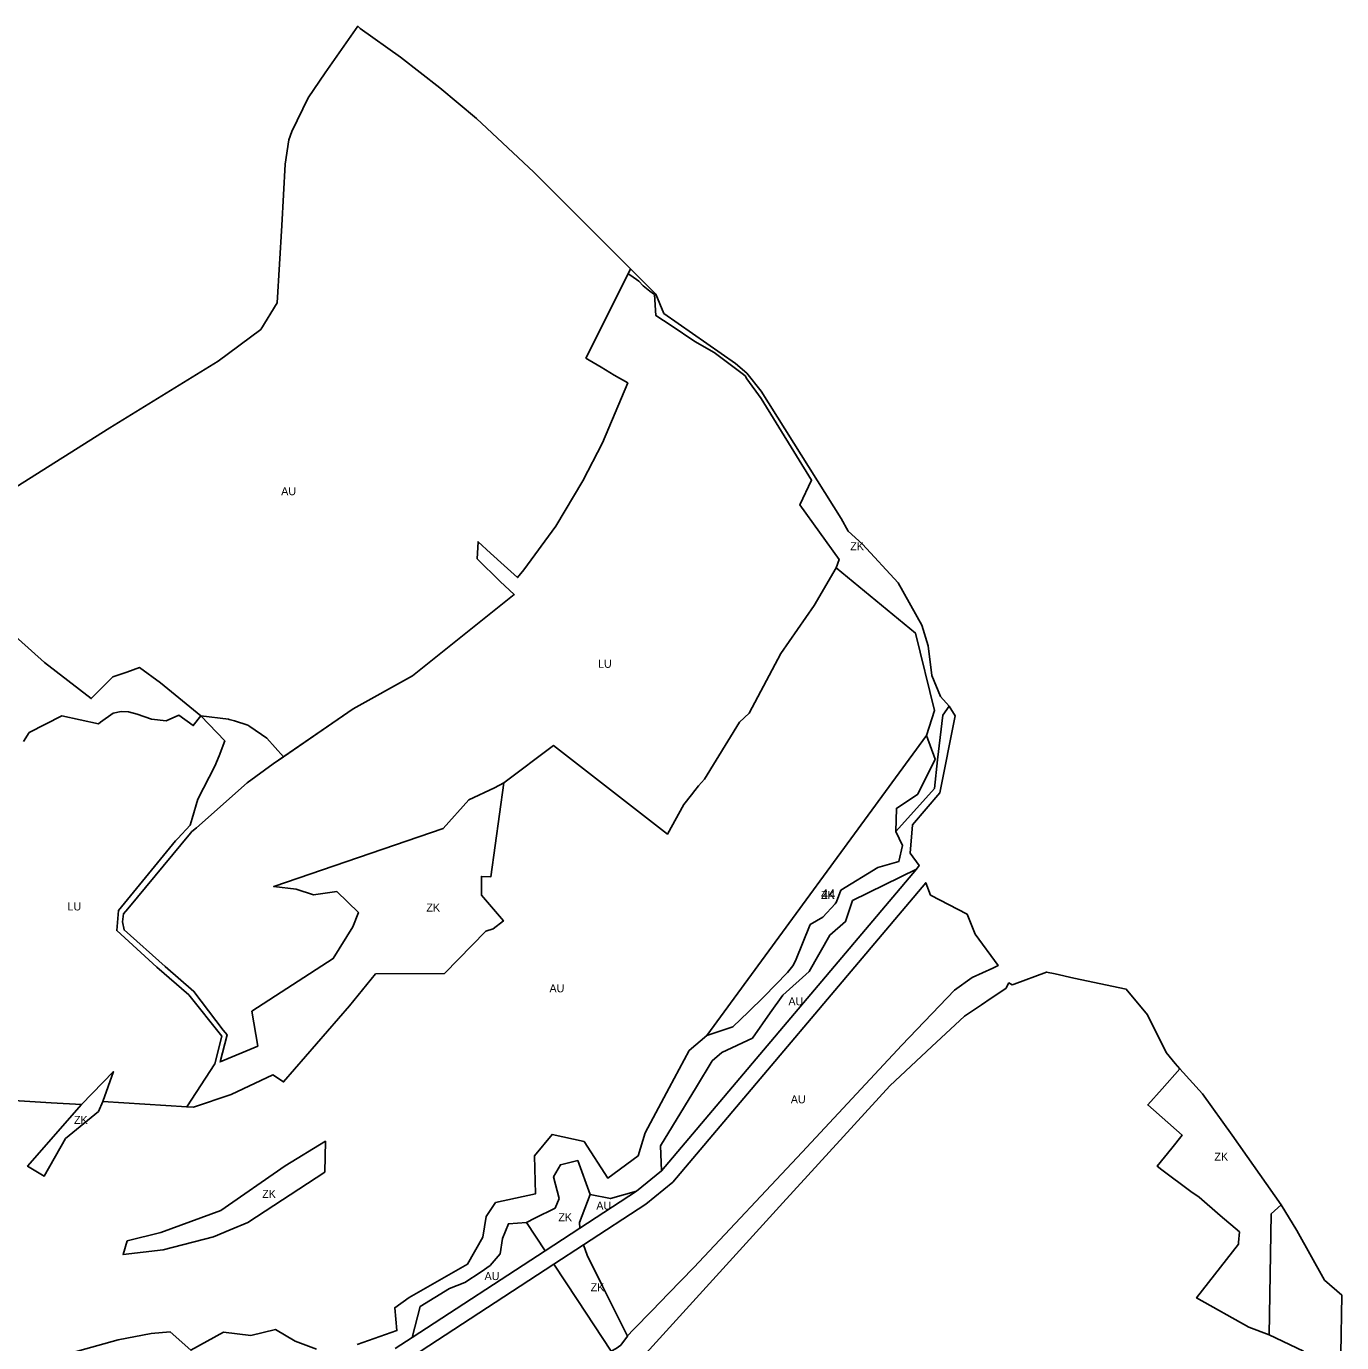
# Model space of a CAD drawing. Extents: x -521261 to -517465, y -1182764 to -1179456.
# Drawn here: x -519568 to -518746, y -1180279 to -1179456 of the extents above; entities that cross this region are included whole.
import ezdxf

# ---------------------------------------------------------------- set-up
doc = ezdxf.new("R2010")
doc.units = 0
for name, color, linetype in [('90640013', 7, 'Continuous'), ('90710013', 7, 'Continuous'), ('90710023', 7, 'Continuous'), ('90750013', 7, 'Continuous'), ('90770013', 7, 'Continuous'), ('ID_navrh', 7, 'Continuous')]:
    doc.layers.add(name, color=color, linetype=linetype)

msp = doc.modelspace()

# ---------------------------------------------------------------- linework, layer by layer
at = {"layer": '90640013'}
for points in [[(-519361.62, -1180279.74), (-519336.67, -1180271.06), (-519338.06, -1180256.8), (-519329.08, -1180250.31), (-519292.48, -1180229.49), (-519282.89, -1180212.77), (-519280.86, -1180199.88), (-519274.99, -1180191.09), (-519249.97, -1180185.55), (-519250.61, -1180161.86), (-519239.69, -1180148.52), (-519219.72, -1180152.85), (-519204.93, -1180175.78), (-519185.89, -1180161.84), (-519181.51, -1180147.48), (-519166.43, -1180119.32), (-519153.96, -1180096.09), (-519142.9, -1180086.6), (-519126.81, -1180081.34), (-519116.98, -1180071.93), (-519107.29, -1180062.58), (-519092.52, -1180047.19), (-519089.17, -1180043.17), (-519087.64, -1180039.96), (-519078.39, -1180017.36), (-519070.55, -1180012.74), (-519062.74, -1180004.36), (-519061.82, -1180003.21), (-519059.13, -1179995.85), (-519035.98, -1179981.57), (-519022.98, -1179978.01), (-519020.57, -1179968.01), (-519024.91, -1179959.15), (-519000.72, -1179932.26), (-518998.7, -1179914.28), (-518995.5, -1179886.53), (-518991.43, -1179880.86), (-518987.68, -1179886.81), (-518997.22, -1179934.93), (-519014.39, -1179955.1), (-519015.83, -1179972.69), (-519010.33, -1179980.49), (-519011.96, -1179982.64), (-519051.9, -1180002.3), (-519056.3, -1180015.44), (-519066.13, -1180023.9), (-519078.94, -1180046.61), (-519095.37, -1180061.41), (-519103.39, -1180072.53), (-519114.42, -1180088.31), (-519133.53, -1180097.26), (-519139.57, -1180102.58), (-519149.41, -1180118.82), (-519171.97, -1180155.54), (-519171.27, -1180171.17), (-519186.97, -1180183.94), (-519203.21, -1180188.59), (-519215.87, -1180186.06), (-519223.62, -1180164.85), (-519234.47, -1180167.48), (-519238.76, -1180175.07), (-519235.32, -1180188.57), (-519237.84, -1180194.65), (-519250.47, -1180200.79), (-519255.66, -1180203.54), (-519267, -1180204.34), (-519270.72, -1180213.62), (-519272.1, -1180223.08), (-519278.49, -1180230.4), (-519284, -1180234.4), (-519294.17, -1180241.09), (-519303.81, -1180244.74), (-519322.14, -1180255.98), (-519327.14, -1180275.48), (-519337.72, -1180282.23)], [(-519540.12, -1180284.95), (-519510.88, -1180276.77), (-519490.4, -1180273), (-519478.49, -1180271.77), (-519465.42, -1180283.42), (-519445.16, -1180272.07), (-519428.03, -1180274.15), (-519412.68, -1180270.41), (-519400.33, -1180277.79), (-519386.97, -1180282.76)]]:
    msp.add_lwpolyline(points, dxfattribs=at)
at = {"layer": '90710013'}
for points in [[(-519077.44, -1179739.61), (-519109.05, -1179688.57), (-519117.88, -1179676.19), (-519119.05, -1179674.41), (-519120.9, -1179672.9), (-519138.3, -1179659.87), (-519150.46, -1179652.92), (-519165.33, -1179642.89), (-519174.76, -1179636.77), (-519175.76, -1179623.57), (-519178.68, -1179621.38), (-519182.72, -1179618.14), (-519185.56, -1179615.32), (-519190.55, -1179611.67), (-519192.16, -1179610.6), (-519190.638, -1179607.556), (-519174.91, -1179623.36), (-519169.82, -1179635.35), (-519124.96, -1179666.62), (-519118.02, -1179672.77), (-519109.01, -1179683.98), (-519058.98, -1179763.47), (-519054.55, -1179771.52), (-519045.59, -1179779.49), (-519023.39, -1179803.85), (-519008.51, -1179830.31), (-519004.59, -1179843.04), (-519002.37, -1179861.74), (-518996.87, -1179874.86), (-518991.43, -1179880.86), (-518995.5, -1179886.53), (-518998.7, -1179914.28), (-519000.72, -1179932.26), (-519024.91, -1179959.15), (-519024.41, -1179944.72), (-519011.15, -1179935.91), (-519000.25, -1179913.89), (-519005.7, -1179899.23), (-519000.65, -1179883.5), (-519012.56, -1179835.21), (-519062.03, -1179794.29), (-519060.32, -1179789.23), (-519084.79, -1179755.04)], [(-519459.24, -1179886.88), (-519441.89, -1179888.96), (-519441.528, -1179889.07), (-519438.293, -1179890.052), (-519429.84, -1179892.62), (-519428.644, -1179893.447), (-519417.99, -1179900.81), (-519407.638, -1179912.444), (-519414.1, -1179916.88), (-519430.25, -1179928.79), (-519462.01, -1179956.85), (-519464.93, -1179959.26), (-519465.79, -1179960.3), (-519504.86, -1180007.44), (-519507.54, -1180010.68), (-519508.17, -1180015.61), (-519507.22, -1180020.63), (-519481.58, -1180043.5), (-519463.54, -1180059.07), (-519445.23, -1180083.38), (-519442.84, -1180086.26), (-519447.23, -1180103.12), (-519423.69, -1180093.23), (-519427.47, -1180071.49), (-519376.5, -1180038.57), (-519364.18, -1180018.83), (-519360.73, -1180009.86), (-519374.34, -1179996.63), (-519388.92, -1179998.74), (-519399.63, -1179995.3), (-519413.72, -1179993.61), (-519307.71, -1179957.39), (-519291.7, -1179939.47), (-519275.76, -1179931.8), (-519269.76, -1179928.77), (-519277.89, -1179987.4), (-519283.91, -1179987.19), (-519283.83, -1179998.93), (-519270.16, -1180015.03), (-519276.5, -1180019.95), (-519281.14, -1180021.48), (-519306.866, -1180047.851), (-519349.98, -1180048.21), (-519366.43, -1180068.13), (-519407.49, -1180115.69), (-519414.22, -1180111.31), (-519440.26, -1180123.58), (-519463.81, -1180131.52), (-519468.1, -1180131.3), (-519450.45, -1180104.27), (-519446.2, -1180087.16), (-519466.73, -1180061.32), (-519486.79, -1180043.85), (-519511.79, -1180021.04), (-519510.74, -1180008.47), (-519475.05, -1179965.04), (-519473.6, -1179963.48), (-519465.85, -1179955.12), (-519464.73, -1179951.12), (-519461.1, -1179938.97), (-519450.42, -1179918.23), (-519447.82, -1179911.81), (-519444.29, -1179902.47)], [(-518858.5, -1180170.71), (-518861.395, -1180168.391), (-518852.28, -1180156.99), (-518845.86, -1180148.96), (-518867.331, -1180130.056), (-518858.394, -1180120.037), (-518847.22, -1180107.51), (-518833.18, -1180123.22), (-518814.68, -1180148.98), (-518784, -1180192.42), (-518790.12, -1180198.06), (-518791.47, -1180273.65), (-518804.19, -1180268.99), (-518836.78, -1180250.69), (-518810.64, -1180217), (-518810.54, -1180215.99), (-518810.04, -1180209.46), (-518822.15, -1180199.1), (-518835.28, -1180187.7), (-518840.33, -1180184.24)], [(-519567.6, -1180168.37), (-519533.89, -1180129.76), (-519513.9, -1180109.18), (-519520.52, -1180127.81), (-519523.23, -1180134.24), (-519543.8, -1180151.09), (-519557.25, -1180174.62)], [(-519381.36, -1180152.77), (-519381.679, -1180172.072), (-519429.9, -1180203.56), (-519440.826, -1180208.122), (-519451.31, -1180212.5), (-519482.7, -1180220.61), (-519507.874, -1180223.575), (-519505.23, -1180215.09), (-519484.18, -1180209.73), (-519446.74, -1180196.02), (-519406.62, -1180168.03)], [(-519244.032, -1180221.205), (-519255.66, -1180203.54), (-519250.47, -1180200.79), (-519237.84, -1180194.65), (-519235.32, -1180188.57), (-519238.76, -1180175.07), (-519234.47, -1180167.48), (-519223.62, -1180164.85), (-519215.87, -1180186.06), (-519222.55, -1180203.47), (-519222.249, -1180206.979)], [(-519223.962, -1180251.695), (-519238.561, -1180229.516), (-519220.038, -1180217.438), (-519217.87, -1180223.87), (-519208.134, -1180243.38), (-519196.738, -1180266.217), (-519192.584, -1180274.543), (-519196.77, -1180280.19), (-519199.69, -1180282.36), (-519202.667, -1180284.047)]]:
    msp.add_lwpolyline(points, close=True, dxfattribs=at)
msp.add_lwpolyline([(-519589.63, -1179824.32), (-519556.92, -1179853.62), (-519527.72, -1179876.1), (-519521.66, -1179869.8), (-519514.27, -1179862.4), (-519505.44, -1179859.57), (-519497.57, -1179856.71), (-519484.38, -1179866.3), (-519459.24, -1179886.88), (-519464.04, -1179892.98), (-519472.93, -1179886.51), (-519480.93, -1179890.03), (-519490.15, -1179888.97), (-519499.07, -1179885.79), (-519504.39, -1179884.47), (-519509.1, -1179884.18), (-519514.11, -1179885.13), (-519521.99, -1179890.73), (-519523.27, -1179891.82), (-519546.18, -1179886.94), (-519566.55, -1179897.34), (-519570.09, -1179903.01)], dxfattribs=at)
at = {"layer": '90710023'}
msp.add_lwpolyline([(-519142.9, -1180086.6), (-519005.7, -1179899.23), (-519000.25, -1179913.89), (-519011.15, -1179935.91), (-519024.41, -1179944.72), (-519024.91, -1179959.15), (-519020.57, -1179968.01), (-519022.98, -1179978.01), (-519035.98, -1179981.57), (-519059.13, -1179995.85), (-519061.82, -1180003.21), (-519062.74, -1180004.36), (-519070.55, -1180012.74), (-519078.39, -1180017.36), (-519087.64, -1180039.96), (-519089.17, -1180043.17), (-519092.52, -1180047.19), (-519107.29, -1180062.58), (-519116.98, -1180071.93), (-519126.81, -1180081.34)], close=True, dxfattribs=at)
at = {"layer": '90750013'}
for points in [[(-519574.82, -1179743.99), (-519516.1, -1179706.88), (-519448.52, -1179665.15), (-519421.79, -1179645.43), (-519411.44, -1179628.84), (-519408.63, -1179580.37), (-519406.46, -1179542.05), (-519404.28, -1179526.89), (-519402.45, -1179521.61), (-519392.24, -1179500.69), (-519381.57, -1179484.98), (-519361.21, -1179455.95), (-519359.72, -1179457.23), (-519334.45, -1179475.21), (-519309.94, -1179494.33), (-519287, -1179513.62), (-519251.17, -1179547.13), (-519199.84, -1179598.31), (-519190.638, -1179607.556), (-519192.16, -1179610.6), (-519218.52, -1179663.34), (-519216.58, -1179664.63), (-519208.94, -1179668.99), (-519200.9, -1179673.95), (-519192.45, -1179678.83), (-519208.08, -1179716.23), (-519220.4, -1179740.02), (-519237.39, -1179768.34), (-519257.44, -1179795.7), (-519261.34, -1179800.45), (-519269.7, -1179792.92), (-519278.09, -1179785.19), (-519285.96, -1179778.08), (-519286.57, -1179788.67), (-519272.15, -1179802.97), (-519263.31, -1179810.97), (-519326.89, -1179861.96), (-519363.99, -1179882.48), (-519407.638, -1179912.444), (-519417.99, -1179900.81), (-519428.644, -1179893.447), (-519429.84, -1179892.62), (-519438.293, -1179890.052), (-519441.528, -1179889.07), (-519441.89, -1179888.96), (-519459.24, -1179886.88), (-519484.38, -1179866.3), (-519497.57, -1179856.71), (-519505.44, -1179859.57), (-519514.27, -1179862.4), (-519521.66, -1179869.8), (-519527.72, -1179876.1), (-519556.92, -1179853.62), (-519589.63, -1179824.32)], [(-519619.68, -1180124.59), (-519552.72, -1180128.66), (-519533.89, -1180129.76), (-519567.6, -1180168.37), (-519557.25, -1180174.62), (-519543.8, -1180151.09), (-519523.23, -1180134.24), (-519520.52, -1180127.81), (-519468.1, -1180131.3), (-519463.81, -1180131.52), (-519440.26, -1180123.58), (-519414.22, -1180111.31), (-519407.49, -1180115.69), (-519366.43, -1180068.13), (-519349.98, -1180048.21), (-519306.866, -1180047.851), (-519281.14, -1180021.48), (-519276.5, -1180019.95), (-519270.16, -1180015.03), (-519283.83, -1179998.93), (-519283.91, -1179987.19), (-519277.89, -1179987.4), (-519269.76, -1179928.77), (-519238.71, -1179905.52), (-519167.62, -1179960.77), (-519157.29, -1179942.3), (-519152.52, -1179936.19), (-519150.51, -1179933.54), (-519148.09, -1179930.61), (-519144.52, -1179926.38), (-519122.54, -1179890.93), (-519116.52, -1179885.29), (-519096.71, -1179848.01), (-519075.85, -1179817.84), (-519062.03, -1179794.29), (-519012.56, -1179835.21), (-519000.65, -1179883.5), (-519005.7, -1179899.23), (-519142.9, -1180086.6), (-519153.96, -1180096.09), (-519166.43, -1180119.32), (-519181.51, -1180147.48), (-519185.89, -1180161.84), (-519204.93, -1180175.78), (-519219.72, -1180152.85), (-519239.69, -1180148.52), (-519250.61, -1180161.86), (-519249.97, -1180185.55), (-519274.99, -1180191.09), (-519280.86, -1180199.88), (-519282.89, -1180212.77), (-519292.48, -1180229.49), (-519329.08, -1180250.31), (-519338.06, -1180256.8), (-519336.67, -1180271.06), (-519361.62, -1180279.74)], [(-519185.02, -1180289.7), (-519143.34, -1180243.85), (-519095.46, -1180191.17), (-519028.54, -1180118.15), (-519002.39, -1180093.57), (-518981.94, -1180074.6), (-518971.19, -1180067.41), (-518965.2, -1180063.4), (-518956.07, -1180057.3), (-518954.15, -1180053.76), (-518952.1, -1180054.93), (-518950.88, -1180054.57), (-518930.62, -1180047.06), (-518925.25, -1180048.07), (-518913.62, -1180050.8), (-518880.77, -1180057.74), (-518867.6, -1180073.76), (-518855.92, -1180097.31), (-518850.28, -1180104.06), (-518847.22, -1180107.51), (-518858.394, -1180120.037), (-518867.331, -1180130.056), (-518845.86, -1180148.96), (-518852.28, -1180156.99), (-518861.395, -1180168.391), (-518858.5, -1180170.71), (-518840.33, -1180184.24), (-518835.28, -1180187.7), (-518822.15, -1180199.1), (-518810.04, -1180209.46), (-518810.54, -1180215.99), (-518810.64, -1180217), (-518836.78, -1180250.69), (-518804.19, -1180268.99), (-518791.47, -1180273.65), (-518769.97, -1180283.94)], [(-519332.465, -1180290.741), (-519238.561, -1180229.516), (-519223.962, -1180251.695), (-519202.667, -1180284.047)], [(-519386.97, -1180282.76), (-519400.33, -1180277.79), (-519412.68, -1180270.41), (-519428.03, -1180274.15), (-519445.16, -1180272.07), (-519465.42, -1180283.42), (-519478.49, -1180271.77), (-519490.4, -1180273), (-519510.88, -1180276.77), (-519540.12, -1180284.95)]]:
    msp.add_lwpolyline(points, dxfattribs=at)
for points in [[(-519011.96, -1179982.64), (-519171.27, -1180171.17), (-519171.97, -1180155.54), (-519149.41, -1180118.82), (-519139.57, -1180102.58), (-519133.53, -1180097.26), (-519114.42, -1180088.31), (-519103.39, -1180072.53), (-519095.37, -1180061.41), (-519078.94, -1180046.61), (-519066.13, -1180023.9), (-519056.3, -1180015.44), (-519051.9, -1180002.3)], [(-519220.038, -1180217.438), (-519181.068, -1180192.03), (-519164.235, -1180178.338), (-519006.122, -1179991.224), (-519003.12, -1179998.88), (-518980.32, -1180010.87), (-518975.15, -1180023.34), (-518960.91, -1180042.97), (-518962.96, -1180043.91), (-518964.28, -1180044.51), (-518977.04, -1180050.38), (-518988.12, -1180058.41), (-519021.15, -1180092.68), (-519083.4, -1180159.52), (-519151.14, -1180231.61), (-519166.92, -1180247.95), (-519177.22, -1180258.6), (-519188.71, -1180270.5), (-519192.5, -1180274.43), (-519192.584, -1180274.543), (-519196.738, -1180266.217), (-519208.134, -1180243.38), (-519217.87, -1180223.87)], [(-519381.679, -1180172.072), (-519381.36, -1180152.77), (-519406.62, -1180168.03), (-519446.74, -1180196.02), (-519484.18, -1180209.73), (-519505.23, -1180215.09), (-519507.874, -1180223.575), (-519482.7, -1180220.61), (-519451.31, -1180212.5), (-519440.826, -1180208.122), (-519429.9, -1180203.56)], [(-519222.249, -1180206.979), (-519222.55, -1180203.47), (-519215.87, -1180186.06), (-519203.21, -1180188.59), (-519186.97, -1180183.94)], [(-519244.032, -1180221.205), (-519327.14, -1180275.48), (-519322.14, -1180255.98), (-519303.81, -1180244.74), (-519294.17, -1180241.09), (-519284, -1180234.4), (-519278.49, -1180230.4), (-519272.1, -1180223.08), (-519270.72, -1180213.62), (-519267, -1180204.34), (-519255.66, -1180203.54)]]:
    msp.add_lwpolyline(points, close=True, dxfattribs=at)
at = {"layer": '90770013'}
msp.add_lwpolyline([(-519447.23, -1180103.12), (-519442.84, -1180086.26), (-519445.23, -1180083.38), (-519463.54, -1180059.07), (-519481.58, -1180043.5), (-519507.22, -1180020.63), (-519508.17, -1180015.61), (-519507.54, -1180010.68), (-519504.86, -1180007.44), (-519465.79, -1179960.3), (-519464.93, -1179959.26), (-519462.01, -1179956.85), (-519430.25, -1179928.79), (-519414.1, -1179916.88), (-519363.99, -1179882.48), (-519326.89, -1179861.96), (-519263.31, -1179810.97), (-519272.15, -1179802.97), (-519286.57, -1179788.67), (-519285.96, -1179778.08), (-519278.09, -1179785.19), (-519269.7, -1179792.92), (-519261.34, -1179800.45), (-519257.44, -1179795.7), (-519237.39, -1179768.34), (-519220.4, -1179740.02), (-519208.08, -1179716.23), (-519192.45, -1179678.83), (-519200.9, -1179673.95), (-519208.94, -1179668.99), (-519216.58, -1179664.63), (-519218.52, -1179663.34), (-519192.16, -1179610.6), (-519190.55, -1179611.67), (-519185.56, -1179615.32), (-519182.72, -1179618.14), (-519178.68, -1179621.38), (-519175.76, -1179623.57), (-519174.76, -1179636.77), (-519165.33, -1179642.89), (-519150.46, -1179652.92), (-519138.3, -1179659.87), (-519120.9, -1179672.9), (-519119.05, -1179674.41), (-519117.88, -1179676.19), (-519109.05, -1179688.57), (-519077.44, -1179739.61), (-519084.79, -1179755.04), (-519060.32, -1179789.23), (-519062.03, -1179794.29), (-519075.85, -1179817.84), (-519096.71, -1179848.01), (-519116.52, -1179885.29), (-519122.54, -1179890.93), (-519144.52, -1179926.38), (-519148.09, -1179930.61), (-519150.51, -1179933.54), (-519152.52, -1179936.19), (-519157.29, -1179942.3), (-519167.62, -1179960.77), (-519238.71, -1179905.52), (-519269.76, -1179928.77), (-519275.76, -1179931.8), (-519291.7, -1179939.47), (-519307.71, -1179957.39), (-519413.72, -1179993.61), (-519399.63, -1179995.3), (-519388.92, -1179998.74), (-519374.34, -1179996.63), (-519360.73, -1180009.86), (-519364.18, -1180018.83), (-519376.5, -1180038.57), (-519427.47, -1180071.49), (-519423.69, -1180093.23)], close=True, dxfattribs=at)
for points in [[(-519570.09, -1179903.01), (-519566.55, -1179897.34), (-519546.18, -1179886.94), (-519523.27, -1179891.82), (-519521.99, -1179890.73), (-519514.11, -1179885.13), (-519509.1, -1179884.18), (-519504.39, -1179884.47), (-519499.07, -1179885.79), (-519490.15, -1179888.97), (-519480.93, -1179890.03), (-519472.93, -1179886.51), (-519464.04, -1179892.98), (-519459.24, -1179886.88), (-519444.29, -1179902.47), (-519447.82, -1179911.81), (-519450.42, -1179918.23), (-519461.1, -1179938.97), (-519464.73, -1179951.12), (-519465.85, -1179955.12), (-519473.6, -1179963.48), (-519475.05, -1179965.04), (-519510.74, -1180008.47), (-519511.79, -1180021.04), (-519486.79, -1180043.85), (-519466.73, -1180061.32), (-519446.2, -1180087.16), (-519450.45, -1180104.27), (-519468.1, -1180131.3), (-519520.52, -1180127.81), (-519513.9, -1180109.18), (-519533.89, -1180129.76), (-519552.72, -1180128.66), (-519619.68, -1180124.59)], [(-518769.97, -1180283.94), (-518791.47, -1180273.65), (-518790.12, -1180198.06), (-518784, -1180192.42), (-518774.14, -1180208.57), (-518756.96, -1180239.5), (-518746.13, -1180248.91), (-518746.71, -1180285.66)]]:
    msp.add_lwpolyline(points, dxfattribs=at)

# ---------------------------------------------------------------- texts
at = {"layer": '90710013'}
for rotation, p in [(360, (-519053.298, -1179783.353)), (0, (-519318.26, -1180009.2)), (360, (-519538.535, -1180141.9)), (360, (-518825.665, -1180164.866)), (0, (-519420.914, -1180188.173)), (0, (-519235.765, -1180202.725)), (360, (-519215.572, -1180246.457))]:
    msp.add_text('ZK', height=5, rotation=rotation, dxfattribs=at).set_placement(p)
at = {"layer": '90710023'}
msp.add_text('ZK', height=5, rotation=360, dxfattribs=at).set_placement((-519071.575, -1180001.269))
at = {"layer": '90750013'}
for rotation, p in [(360, (-519409.022, -1179749.006)), (360, (-519241.324, -1180059.685)), (360, (-519091.965, -1180067.831)), (360, (-519090.474, -1180129.048)), (0, (-519212.043, -1180195.46)), (360, (-519281.915, -1180239.51))]:
    msp.add_text('AU', height=5, rotation=rotation, dxfattribs=at).set_placement(p)
at = {"layer": '90770013'}
for p in [(-519210.972, -1179856.86), (-519542.56, -1180008.482)]:
    msp.add_text('LU', height=5, rotation=0, dxfattribs=at).set_placement(p)
at = {"layer": 'ID_navrh'}
msp.add_text('44', height=6, rotation=360, dxfattribs=at).set_placement((-519071.575, -1180001.269))

doc.saveas('drawing.dxf')
